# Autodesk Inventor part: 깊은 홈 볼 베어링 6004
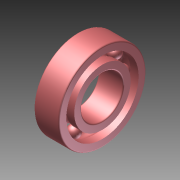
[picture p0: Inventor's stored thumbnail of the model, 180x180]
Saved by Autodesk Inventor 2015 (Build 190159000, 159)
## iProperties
Created: 2026-04
Part Number: 깊은 홈 볼 베어링 6004
Material: 일반
Document SubType Name: Modeling
Designer: User
Density: 1 g/cm^3
Appearance: 기본값
Author: User
Author: jhkim
Description: 깊은 그루브 볼 베어링
Creation Date: 2026-03-26
Sending System: Autodesk Inventor 2026
Preprocessor: ST-DEVELOPER v20.1
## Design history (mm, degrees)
node "깊은 홈 볼 베어링 60041"
body "Solid1"
node "Solid1_1"
node "Solid1_2"
node "Solid1_3"
node "Solid1_4"
node "Solid1_5"
node "Solid1_6"
node "Solid1_7"
node "Solid1_8"
node "Solid1_9"
node "Solid1_10"
node "기준1"
node "기준2"
node "기준3"
node "기준4"
node "기준5"
node "기준6"
node "기준7"
node "기준8"
node "기준9"
node "기준10"
node "기준11"
